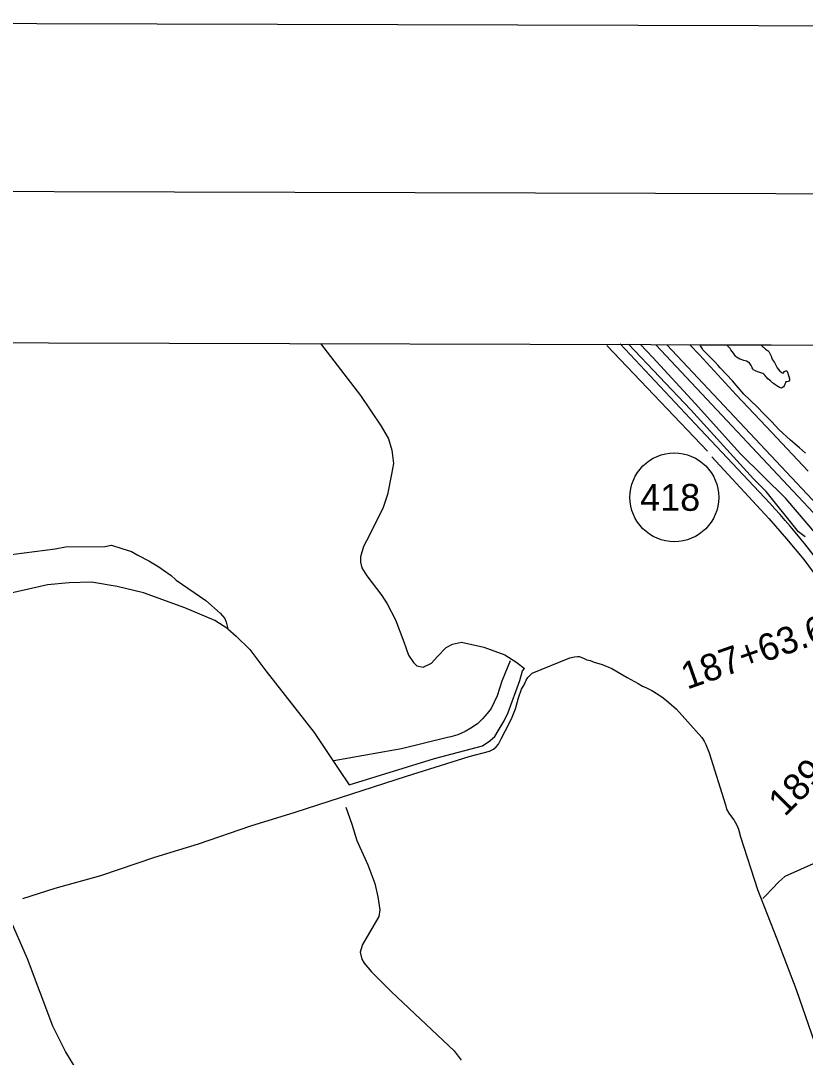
# Model space of a CAD drawing. Extents: x 3161665 to 3199565, y 885729 to 911164.
# Drawn here: x 3166281 to 3169197, y 906728 to 910580 of the extents above; entities that cross this region are included whole.
import ezdxf

# ---------------------------------------------------------------- set-up
doc = ezdxf.new("R2010")
doc.units = 0
for name, color, linetype in [('G-ANNO-NPLT', 7, 'Continuous'), ('V-ANNO-SYMB', 7, 'Continuous'), ('V-GRID-FRAM', 7, 'Continuous'), ('V-LEVE-TOET', 7, 'Continuous'), ('V-ROAD-CNTR', 7, 'Continuous'), ('V-ROAD-IDEN', 7, 'Continuous'), ('V-SITE-VEGE', 7, 'Continuous'), ('V-SURV-IDEN', 7, 'Continuous'), ('V-SURV-LINE', 7, 'Continuous'), ('V-TOPO-SHOR', 7, 'Continuous'), ('V-WETL-SWMP', 7, 'Continuous')]:
    doc.layers.add(name, color=color, linetype=linetype)

msp = doc.modelspace()

# ---------------------------------------------------------------- linework, layer by layer
at = {"layer": 'G-ANNO-NPLT'}
msp.add_lwpolyline([(3162248.3, 886413.8), (3198914.8, 886312.5), (3198981.6, 910479), (3162315.1, 910580.4)], close=True, dxfattribs=at)
at = {"layer": 'V-ANNO-SYMB'}
msp.add_lwpolyline([(3165000.2, 887031.2), (3198083.2, 886939.8), (3198146.6, 909856.3), (3165063.5, 909947.7), (3165000.2, 887031.2)], dxfattribs=at)
at = {"layer": 'V-GRID-FRAM'}
msp.add_lwpolyline([(3165935.6, 909383.8), (3197271.3, 909297.2), (3197229, 891108.8), (3165877.4, 891195.5), (3165935.6, 909383.8)], dxfattribs=at)
at = {"layer": 'V-LEVE-TOET'}
for points in [[(3169276.3, 908627.2), (3169124.9, 908805), (3168956.9, 908971), (3168788.8, 909158.1), (3168631.4, 909328.4), (3168585.2, 909376.5)], [(3168768.4, 909376), (3168803.9, 909338.1), (3168940.4, 909190.2), (3169052.1, 909072.5), (3169208.2, 908906.5)]]:
    msp.add_lwpolyline(points, dxfattribs=at)
at = {"layer": 'V-ROAD-CNTR'}
msp.add_lwpolyline([(3168509.1, 909379.2), (3168788.3, 909082), (3169046.4, 908808)], dxfattribs=at)
msp.add_arc((3166713.5, 906635.2), 3188.1, 34.7813, 42.9642, dxfattribs=at)
at = {"layer": 'V-ROAD-IDEN'}
msp.add_circle((3168710.9, 908808.8), 165, dxfattribs=at)
at = {"layer": 'V-SITE-VEGE'}
for p, q in [((3168808.1, 909371.5), (3168806.3, 909375.9)), ((3168806.3, 909375.9), (3170058.8, 909372.4)), ((3168815, 909360.3), (3168808.1, 909371.5)), ((3168816.8, 909357.6), (3168815, 909360.3)), ((3168836.6, 909337.5), (3168816.8, 909357.6)), ((3168855, 909318.5), (3168836.6, 909337.5)), ((3168862.4, 909311), (3168855, 909318.5)), ((3168873.9, 909298.9), (3168862.4, 909311)), ((3168881.7, 909290.1), (3168873.9, 909298.9)), ((3168926.4, 909242.1), (3168881.7, 909290.1)), ((3168947.5, 909216.6), (3168926.4, 909242.1)), ((3168969.1, 909192.8), (3168947.5, 909216.6)), ((3168991.2, 909171.4), (3168969.1, 909192.8)), ((3169021.6, 909143), (3168991.2, 909171.4)), ((3169040, 909123.5), (3169021.6, 909143)), ((3169072.7, 909089.5), (3169040, 909123.5)), ((3169099.4, 909061.1), (3169072.7, 909089.5)), ((3169143.1, 909021.1), (3169099.4, 909061.1)), ((3169176.3, 908992.6), (3169143.1, 909021.1)), ((3169198.4, 908973.1), (3169176.3, 908992.6))]:
    msp.add_line(p, q, dxfattribs=at)
at = {"layer": 'V-SURV-LINE'}
for points in [[(3169549.2, 908409.6), (3168641.8, 909376.3)], [(3168683, 909376.2), (3169571, 908430.1)]]:
    msp.add_lwpolyline(points, dxfattribs=at)
at = {"layer": 'V-TOPO-SHOR'}
msp.add_line((3168459.6, 909373.6), (3168833.5, 908981), dxfattribs=at)
for points in [[(3167395.4, 909381.3), (3167543.8, 909187.2), (3167620.7, 909073.6), (3167648.4, 909026.4), (3167660.1, 908984.6), (3167667.5, 908934.3), (3167659.9, 908894.7), (3167644.7, 908819.8), (3167628.6, 908771.6), (3167578, 908667.9), (3167555.4, 908626.2), (3167544.6, 908587.7), (3167544.6, 908568.4), (3167548.8, 908547), (3167568, 908517), (3167623.6, 908444), (3167643.8, 908413), (3167674.8, 908354), (3167705.6, 908271.5), (3167722.6, 908222.2), (3167740.8, 908195.4), (3167753.6, 908182.5), (3167777.1, 908178.2), (3167808.2, 908192), (3167829.7, 908215.6), (3167863, 908250.8), (3167886.5, 908263.6), (3167919.7, 908271), (3168002.1, 908252.6), (3168080.2, 908223.6), (3168125.1, 908195.6), (3168154, 908173.1)], [(3169197.4, 908662.3), (3169172.2, 908681), (3169051.8, 908830.6), (3169005.5, 908877.1), (3168770.5, 909135.1), (3168539.8, 909378.7)], [(3168850.5, 908959.5), (3169062, 908730), (3169128.2, 908654.9), (3169192.3, 908577.6), (3169226.5, 908530.5), (3169252.1, 908491.9), (3169393, 908294.6), (3169450.6, 908210.9), (3169512.5, 908140.1), (3169576.6, 908067.2), (3169843.7, 907798.9), (3169986.8, 907663.7), (3170141.7, 907517.8), (3170202.6, 907452.3), (3170242.1, 907395.5), (3170282.6, 907305.5), (3170306, 907217.7), (3170311.2, 907182.3), (3170315.4, 907133.1), (3170312.1, 907065.6)], [(3166217.1, 908592.7), (3166409.9, 908618), (3166447.4, 908625.4), (3166594, 908626.2), (3166618.7, 908631.5), (3166657.2, 908618.5), (3166693.6, 908607.8), (3166716, 908593.8), (3166757.7, 908573.4), (3166795.1, 908550.8), (3166812.2, 908537.9), (3166840, 908518.6), (3166857.1, 908503.5), (3166859.3, 908501.4), (3166969.4, 908425.1), (3167022.8, 908377.9), (3167039.9, 908358.6), (3167045.2, 908344.7), (3167050.5, 908320), (3167002.4, 908351.2), (3166891.2, 908398.6), (3166738.2, 908453.5), (3166639.7, 908477.3), (3166544.5, 908493.5), (3166461, 908491.6), (3166380.7, 908484.3), (3166348.5, 908475.8), (3166089.3, 908418.5)], [(3167050.5, 908320), (3167081.5, 908293.2), (3167132.8, 908243.9), (3167192.6, 908164.5), (3167371.9, 907935), (3167463.7, 907797.8), (3167502.1, 907739.9), (3167819.2, 907837.7), (3167998.1, 907885.4), (3168024.9, 907903.6), (3168043.2, 907919.6), (3168056.1, 907941), (3168078.6, 907978.4), (3168092.6, 908009.4), (3168136.8, 908128.2), (3168146.5, 908163.5), (3168154, 908173.1)], [(3166289.4, 907318.3), (3166409.6, 907355.8), (3166579.1, 907402.8), (3166780.2, 907471.4), (3166942, 907520.5), (3167136.6, 907587.8), (3167301.4, 907639.1), (3167511.9, 907706.8), (3167715.8, 907772.7), (3167947.8, 907845.6), (3168023.5, 907865.1), (3168039.1, 907872.3), (3168048.7, 907881), (3168057.3, 907891.9), (3168067, 907910.9), (3168097.4, 907968.7), (3168107.7, 907991.6), (3168120.2, 908023), (3168131.6, 908063.8), (3168142.8, 908095.8), (3168152.2, 908111.6), (3168160, 908129.2), (3168165.8, 908138.7), (3168173.1, 908147.2), (3168182.9, 908155.9), (3168322.2, 908211.8), (3168340.1, 908215.6), (3168350.3, 908217.9), (3168357.2, 908217.7), (3168373.4, 908210.7), (3168385.5, 908205.2), (3168398.3, 908202.2), (3168412.9, 908196.7), (3168442.9, 908187.8), (3168478.6, 908172.7), (3168535.7, 908139.5), (3168575.8, 908116.7), (3168592, 908107.1), (3168607.4, 908100.5), (3168627, 908091.1), (3168649.3, 908076.9), (3168669.1, 908063.2), (3168690.2, 908046.6), (3168719.1, 908021.5), (3168812.8, 907916.3), (3168821.6, 907902.7), (3168828.1, 907889.8), (3168839.9, 907859.7), (3168901.4, 907666.6), (3168905.1, 907649.5), (3168913.6, 907634.4), (3168919, 907626.9), (3168932.1, 907610.7), (3168937, 907602), (3168944.2, 907587.9), (3168948.8, 907575.1), (3168957, 907547.4), (3169020.1, 907351.8), (3169092, 907167.4), (3169163.1, 906979.3), (3169232, 906782.1)], [(3168100.5, 908201), (3168069.3, 908125.1), (3168052.1, 908071.6), (3168029.5, 908023.5), (3168015.5, 908005.3), (3167998.3, 907986.1), (3167979, 907966.8), (3167954.4, 907950.8), (3167932.9, 907938), (3167906.1, 907926.3), (3167879.4, 907918.9), (3167867.6, 907915.7), (3167697.2, 907874.3), (3167668.3, 907869), (3167444.5, 907829.9)], [(3167490.1, 907657.4), (3167512.5, 907594.2), (3167530.6, 907533.2), (3167571, 907443.1), (3167597.7, 907373.5), (3167608.2, 907324.2), (3167615.6, 907276), (3167612.4, 907251.4), (3167598.4, 907226.8), (3167552.2, 907146.6), (3167543.6, 907118.8), (3167548.9, 907092), (3167557.4, 907077), (3167585.2, 907044.8), (3167640.7, 906989), (3167657.8, 906971.9), (3167746.5, 906889.2), (3167891.8, 906751.9), (3167918.5, 906716.5)], [(3169801.2, 907454.3), (3169712.1, 907389.2), (3169696.1, 907381.7), (3169676.8, 907373.2), (3169656.4, 907376.5), (3169607.2, 907387.3), (3169557, 907407.7), (3169505.6, 907427.1), (3169446.8, 907445.4), (3169385.8, 907455.2), (3169308.7, 907468.2), (3169288.4, 907467.2), (3169251.9, 907458.7), (3169238, 907451.3), (3169121.2, 907399.1), (3169099.7, 907379.8), (3169074, 907354.2), (3169051.4, 907329.6), (3169039.6, 907317.9), (3169039.6, 907317.9)], [(3166847.9, 906234.9), (3166760.3, 906327.2), (3166645, 906466.6), (3166605.5, 906521.3), (3166478.4, 906698.3), (3166447.5, 906748.6), (3166400.6, 906843), (3166306.9, 907093.7), (3166238.8, 907250.1)]]:
    msp.add_lwpolyline(points, dxfattribs=at)
at = {"layer": 'V-WETL-SWMP'}
for p, q in [((3168905.3, 909375.6), (3169033.9, 909375.2)), ((3168910.5, 909369.7), (3168905.3, 909375.6)), ((3168917.8, 909362.4), (3168910.5, 909369.7)), ((3168921.4, 909357.1), (3168917.8, 909362.4)), ((3168930.6, 909344.8), (3168921.4, 909357.1)), ((3168937.9, 909333.9), (3168930.6, 909344.8)), ((3169033.9, 909375.2), (3169034.6, 909373.7)), ((3169034.6, 909373.7), (3169038.6, 909369.5)), ((3169038.6, 909369.5), (3169041.7, 909366.6)), ((3169041.7, 909366.6), (3169049.7, 909360.1)), ((3169049.7, 909360.1), (3169056.6, 909355.2)), ((3169056.6, 909355.2), (3169059.2, 909353.5)), ((3169059.2, 909353.5), (3169061.9, 909351.4)), ((3169061.9, 909351.4), (3169069.7, 909335.9)), ((3168941.3, 909329.7), (3168937.9, 909333.9)), ((3168954.8, 909321.9), (3168941.3, 909329.7)), ((3168958.6, 909320.6), (3168954.8, 909321.9)), ((3168964.8, 909319), (3168958.6, 909320.6)), ((3168968.8, 909317.7), (3168964.8, 909319)), ((3168974.1, 909316.5), (3168968.8, 909317.7)), ((3168979.2, 909314.8), (3168974.1, 909316.5)), ((3168985.7, 909311.9), (3168979.2, 909314.8)), ((3168989, 909309.6), (3168985.7, 909311.9)), ((3168991.9, 909305.8), (3168989, 909309.6)), ((3168993.9, 909302.7), (3168991.9, 909305.8)), ((3168995.9, 909299), (3168993.9, 909302.7)), ((3168998.5, 909294.1), (3168995.9, 909299)), ((3169069.7, 909335.9), (3169071.6, 909331.5)), ((3169071.6, 909331.5), (3169072.5, 909328.1)), ((3169072.5, 909328.1), (3169076.1, 909319.9)), ((3169076.1, 909319.9), (3169082.5, 909309.7)), ((3169082.5, 909309.7), (3169090.6, 909295.2)), ((3169000.3, 909290.1), (3168998.5, 909294.1)), ((3169002.5, 909286.3), (3169000.3, 909290.1)), ((3169005.6, 909281.8), (3169002.5, 909286.3)), ((3169010, 909280.1), (3169005.6, 909281.8)), ((3169014.9, 909277.6), (3169010, 909280.1)), ((3169021.5, 909274.9), (3169014.9, 909277.6)), ((3169024.7, 909273.8), (3169021.5, 909274.9)), ((3169032.4, 909272.2), (3169024.7, 909273.8)), ((3169040.2, 909268.7), (3169032.4, 909272.2)), ((3169043.1, 909266.5), (3169040.2, 909268.7)), ((3169047.3, 909262.4), (3169043.1, 909266.5)), ((3169051, 909258.2), (3169047.3, 909262.4)), ((3169090.6, 909295.2), (3169093.5, 909290.8)), ((3169093.5, 909290.8), (3169103.1, 909278.1)), ((3169103.1, 909278.1), (3169106.2, 909274.8)), ((3169106.2, 909274.8), (3169110.4, 909271.4)), ((3169110.4, 909271.4), (3169115, 909270.1)), ((3169115, 909270.1), (3169120.4, 909276.7)), ((3169120.4, 909276.7), (3169125.7, 909279.1)), ((3169125.7, 909279.1), (3169128.8, 909278.5)), ((3169128.8, 909278.5), (3169131.7, 909273.8)), ((3169131.7, 909273.8), (3169135, 909261.8)), ((3169135, 909261.8), (3169136.5, 909258.5)), ((3169053, 909255.7), (3169051, 909258.2)), ((3169058.4, 909249.8), (3169053, 909255.7)), ((3169068.3, 909242.4), (3169058.4, 909249.8)), ((3169075.9, 909235.1), (3169068.3, 909242.4)), ((3169079.4, 909232), (3169075.9, 909235.1)), ((3169084.3, 909228.2), (3169079.4, 909232)), ((3169095.4, 909220.4), (3169084.3, 909228.2)), ((3169119.2, 909223.4), (3169116.7, 909219.9)), ((3169120.5, 909226.1), (3169119.2, 909223.4)), ((3169121.8, 909229.4), (3169120.5, 909226.1)), ((3169123.6, 909234.7), (3169121.8, 909229.4)), ((3169125.4, 909237.8), (3169123.6, 909234.7)), ((3169129.4, 909237.8), (3169125.4, 909237.8)), ((3169133.8, 909239.1), (3169129.4, 909237.8)), ((3169137.2, 909241.2), (3169133.8, 909239.1)), ((3169136.5, 909258.5), (3169138.8, 909248.9)), ((3169138.3, 909244.3), (3169137.2, 909241.2)), ((3169138.8, 909248.9), (3169138.3, 909244.3)), ((3169101.8, 909217), (3169095.4, 909220.4)), ((3169104.9, 909215.5), (3169101.8, 909217)), ((3169109.4, 909215), (3169104.9, 909215.5)), ((3169113.1, 909216.6), (3169109.4, 909215)), ((3169116.7, 909219.9), (3169113.1, 909216.6))]:
    msp.add_line(p, q, dxfattribs=at)

# ---------------------------------------------------------------- texts
at = {"layer": 'V-ROAD-IDEN'}
msp.add_text('418', height=100, dxfattribs=at).set_placement((3168583.8, 908758.8))
at = {"layer": 'V-SURV-IDEN'}
for s, rotation, p in [('187+63.6', 19.4311, (3168758.1, 908093.7)), ('189+78.5', 45.22, (3169121.5, 907619.2))]:
    msp.add_text(s, height=100, rotation=rotation, dxfattribs=at).set_placement(p)

doc.saveas('drawing.dxf')
